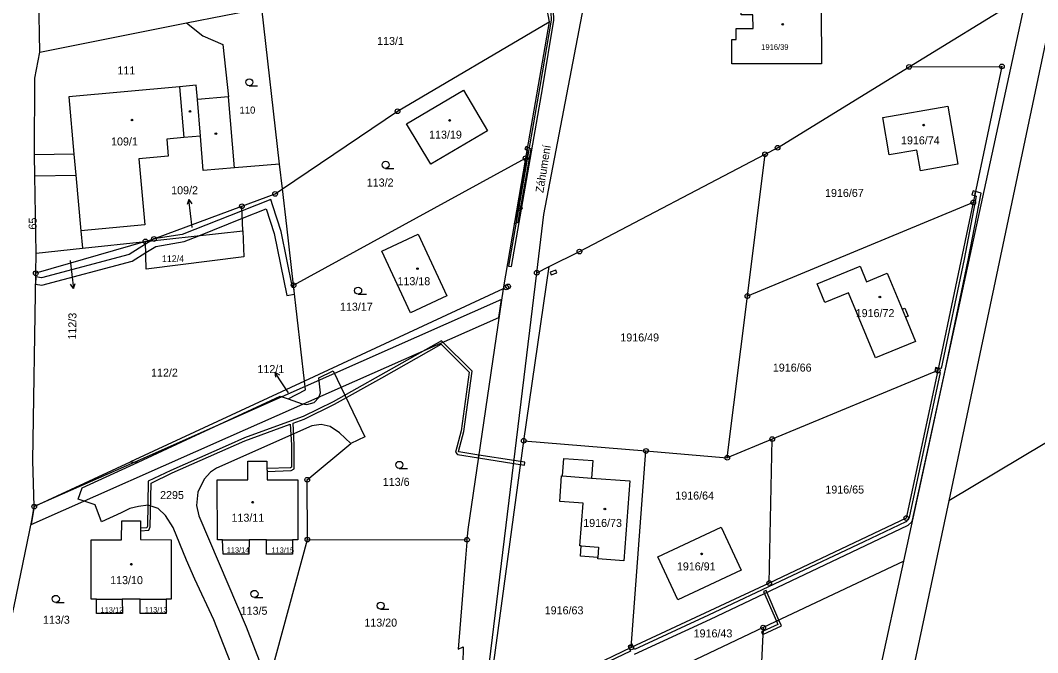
# Model space of a CAD drawing. Extents: x -504988 to -494607, y -1123820 to -1114018.
# Drawn here: x -497515.3 to -497299.3, y -1119789.7 to -1119655.4 of the extents above; entities that cross this region are included whole.
import ezdxf

# ---------------------------------------------------------------- set-up
doc = ezdxf.new("R2010")
doc.units = 0
for name, color, linetype in [('Hranice parcel', 7, 'Continuous'), ('Parcelní čísla', 7, 'Continuous'), ('Pop  PČ popisy', 7, 'Continuous'), ('Vnitřní kresba', 7, 'Continuous'), ('Věcná břemena k části', 7, 'Continuous'), ('Značky bodu BP', 7, 'Continuous'), ('Značky budov', 7, 'Continuous'), ('Značky kultur', 7, 'Continuous')]:
    doc.layers.add(name, color=color, linetype=linetype)

msp = doc.modelspace()

# ---------------------------------------------------------------- linework, layer by layer
at = {"layer": 'Hranice parcel'}
for p, q in [((-497407.59, -1119632.61), (-497403.06, -1119655.71)), ((-497511.18, -1119662.18), (-497511.51, -1119643.57)), ((-497327.77, -1119770.24), (-497301.66, -1119649.94)), ((-497326.62, -1119665.28), (-497301.66, -1119649.94)), ((-497480.03, -1119655.96), (-497464.09, -1119652.83)), ((-497460.28, -1119685.94), (-497464.09, -1119652.83)), ((-497511.18, -1119662.18), (-497480.03, -1119655.96)), ((-497403.06, -1119655.71), (-497408.06, -1119684.69)), ((-497326.62, -1119665.28), (-497306.93, -1119665.18)), ((-497306.93, -1119665.18), (-497313.01, -1119694.07)), ((-497457.32, -1119711.66), (-497408.06, -1119684.69)), ((-497408.06, -1119684.69), (-497412.84, -1119712.42)), ((-497360.96, -1119713.95), (-497357.22, -1119683.85)), ((-497459.67, -1119691.2), (-497460.28, -1119685.94)), ((-497313.01, -1119694.07), (-497360.96, -1119713.95)), ((-497313.01, -1119694.07), (-497320.56, -1119729.78)), ((-497468.09, -1119700.14), (-497468.28, -1119694.88)), ((-497488.77, -1119702.37), (-497468.09, -1119700.14)), ((-497488.77, -1119702.37), (-497512.06, -1119709.13)), ((-497502.14, -1119703.81), (-497488.77, -1119702.37)), ((-497512.06, -1119709.13), (-497511.99, -1119704.87)), ((-497511.99, -1119704.87), (-497502.14, -1119703.81)), ((-497409, -1119736.4), (-497405.68, -1119709.01)), ((-497408.46, -1119744.7), (-497403.07, -1119707.71)), ((-497405.68, -1119709.01), (-497403.07, -1119707.71)), ((-497454.98, -1119732), (-497457.32, -1119711.66)), ((-497412.84, -1119712.42), (-497454.98, -1119732)), ((-497365.23, -1119748.3), (-497360.96, -1119713.95)), ((-497320.56, -1119729.78), (-497355.7, -1119744.33)), ((-497454.98, -1119732), (-497491.96, -1119749.19)), ((-497481.05, -1119744.93), (-497460.19, -1119735.22)), ((-497460.19, -1119735.22), (-497458.47, -1119735.81)), ((-497458.47, -1119735.81), (-497455.5, -1119736.82)), ((-497418.3, -1119813.05), (-497409, -1119736.4)), ((-497490.32, -1119749.21), (-497481.05, -1119744.93)), ((-497408.46, -1119744.7), (-497382.5, -1119746.86)), ((-497355.7, -1119744.33), (-497365.23, -1119748.3)), ((-497356.32, -1119774.9), (-497355.7, -1119744.33)), ((-497385.64, -1119788.59), (-497382.5, -1119746.86)), ((-497382.5, -1119746.86), (-497365.23, -1119748.3)), ((-497512.39, -1119758.68), (-497491.96, -1119749.19)), ((-497502.18, -1119754.7), (-497490.32, -1119749.21)), ((-497491.96, -1119749.19), (-497490.32, -1119749.21)), ((-497472.38, -1119765.73), (-497466.78, -1119765.72)), ((-497463.05, -1119765.72), (-497466.78, -1119765.72)), ((-497463.05, -1119765.72), (-497457.52, -1119765.72)), ((-497463.02, -1119797.51), (-497454.39, -1119765.69)), ((-497454.39, -1119765.69), (-497420.5, -1119765.72)), ((-497327.77, -1119770.24), (-497357.6, -1119784.35)), ((-497340.35, -1119828.18), (-497327.77, -1119770.24)), ((-497356.32, -1119774.9), (-497385.64, -1119788.59)), ((-497499.15, -1119778.3), (-497493.68, -1119778.31)), ((-497489.92, -1119778.31), (-497493.68, -1119778.31)), ((-497489.92, -1119778.31), (-497484.34, -1119778.32)), ((-497357.6, -1119784.35), (-497379.24, -1119794.58)), ((-497357.6, -1119784.35), (-497360.12, -1119837.86))]:
    msp.add_line(p, q, dxfattribs=at)
for points in [[(-496164.18, -1119488.14), (-496312.79, -1119486.99), (-496461.39, -1119485.83), (-496579.64, -1119487.64), (-496697.89, -1119489.45), (-496849, -1119528.49), (-497000.1, -1119567.53), (-497159.17, -1119662.47), (-497318.23, -1119757.42)], [(-497359.78, -1119654.24), (-497362.29, -1119654.26), (-497362.28, -1119646.75), (-497348.25, -1119646.69), (-497348.23, -1119653.04), (-497345.27, -1119653.09), (-497345.26, -1119664.61), (-497364.27, -1119664.64), (-497364.26, -1119659.46), (-497363.35, -1119659.45), (-497363.37, -1119657.14), (-497359.76, -1119657.14), (-497359.78, -1119654.24)], [(-497295.06, -1119646.14), (-497295.74, -1119650.96), (-497318.23, -1119757.42)], [(-497405.68, -1119709.01), (-497404.18, -1119696.66), (-497395.06, -1119648.92)], [(-497480.03, -1119655.96), (-497476.56, -1119658.71), (-497472.36, -1119660.56), (-497471.12, -1119671.68)], [(-497459.67, -1119691.2), (-497435.24, -1119674.7), (-497403.06, -1119655.71)], [(-497511.99, -1119704.87), (-497512.23, -1119688.43), (-497512.34, -1119684), (-497512.24, -1119667.7), (-497511.18, -1119662.18)], [(-497357.22, -1119683.85), (-497354.55, -1119682.45), (-497326.62, -1119665.28)], [(-497471.12, -1119671.68), (-497477.75, -1119672.23), (-497478.01, -1119669.18), (-497481.57, -1119669.5), (-497505.05, -1119671.63), (-497503.95, -1119683.82), (-497503.54, -1119688.26), (-497502.47, -1119700.09), (-497502.14, -1119703.81)], [(-497433.34, -1119677.36), (-497421.27, -1119670.24), (-497416.16, -1119678.85), (-497428.21, -1119685.98), (-497433.34, -1119677.36)], [(-497460.28, -1119685.94), (-497469.86, -1119686.74), (-497471.12, -1119671.68)], [(-497324.18, -1119687.36), (-497325, -1119682.99), (-497330.89, -1119683.98), (-497332.21, -1119676.05), (-497318.41, -1119673.63), (-497316.27, -1119685.98), (-497324.18, -1119687.36)], [(-497403.07, -1119707.71), (-497396.63, -1119704.51), (-497357.22, -1119683.85)], [(-497468.28, -1119694.88), (-497461.23, -1119692.25), (-497459.67, -1119691.2)], [(-497457.32, -1119711.66), (-497458.76, -1119699.13), (-497459.67, -1119691.2)], [(-497488.77, -1119702.37), (-497486.96, -1119701.84), (-497468.28, -1119694.88)], [(-497468.09, -1119700.14), (-497467.89, -1119705.6), (-497488.61, -1119708.26), (-497488.77, -1119702.37)], [(-497438.56, -1119704.39), (-497430.87, -1119700.82), (-497424.76, -1119713.94), (-497432.46, -1119717.52), (-497438.56, -1119704.39)], [(-497512.39, -1119758.68), (-497512.67, -1119748.87), (-497512.06, -1119709.13)], [(-497339.49, -1119713.27), (-497344.54, -1119715.32), (-497346.17, -1119711.36), (-497337.03, -1119707.58), (-497335.67, -1119710.93), (-497331.29, -1119709.11), (-497328.11, -1119716.76), (-497327.55, -1119716.55), (-497326.85, -1119718.24), (-497327.4, -1119718.47), (-497325.28, -1119723.59), (-497333.77, -1119727.11), (-497339.49, -1119713.27)], [(-497412.84, -1119712.42), (-497420.32, -1119763.55), (-497420.5, -1119765.72)], [(-497455.5, -1119736.82), (-497454.51, -1119736.96), (-497452.95, -1119736.54), (-497451.93, -1119735.53), (-497451.62, -1119734.51), (-497451.99, -1119731.35), (-497448.94, -1119729.87), (-497442.2, -1119743.84), (-497445.14, -1119745.27)], [(-497320.56, -1119729.78), (-497327.23, -1119761.11), (-497356.32, -1119774.9)], [(-497458.47, -1119735.81), (-497454.76, -1119733.9), (-497454.98, -1119732)], [(-497445.14, -1119745.27), (-497447.56, -1119743), (-497449.56, -1119741.68), (-497451.47, -1119741.24), (-497453.43, -1119741.49), (-497473.67, -1119750.53), (-497474.95, -1119751.36), (-497476.27, -1119752.82), (-497477.67, -1119755.63), (-497477.95, -1119758.44), (-497477.45, -1119760.62), (-497475.19, -1119765.95), (-497467.37, -1119784.18), (-497464.3, -1119792.28), (-497463.02, -1119797.51)], [(-497454.39, -1119765.69), (-497454.42, -1119752.97), (-497445.14, -1119745.27)], [(-497385.64, -1119788.59), (-497399.15, -1119795.13), (-497401.06, -1119795.52), (-497411.99, -1119794.43), (-497413.82, -1119793.5), (-497414.82, -1119791.78), (-497408.46, -1119744.7)], [(-497472.38, -1119765.73), (-497473.5, -1119765.73), (-497473.53, -1119753.02), (-497471.1, -1119753.01), (-497467.01, -1119753), (-497467, -1119748.99), (-497463.01, -1119749.01), (-497462.92, -1119752.98), (-497456.42, -1119752.98), (-497456.39, -1119765.72), (-497457.52, -1119765.72)], [(-497396.52, -1119766.97), (-497395.83, -1119757.96), (-497400.82, -1119757.59), (-497400.41, -1119752.12), (-497400.21, -1119752.14), (-497399.93, -1119748.44), (-497393.78, -1119748.9), (-497394.06, -1119752.6), (-497385.9, -1119753.22), (-497387.19, -1119770.2), (-497392.74, -1119769.77), (-497392.72, -1119769.49), (-497396.41, -1119769.21), (-497396.23, -1119766.99), (-497396.52, -1119766.97)], [(-497468.93, -1119817.15), (-497469.03, -1119809.5), (-497469.23, -1119795.55), (-497474.27, -1119782.74), (-497478.31, -1119774.06), (-497480.05, -1119770.08), (-497482.92, -1119763.12), (-497484.5, -1119760.57), (-497486.1, -1119759.09), (-497488.21, -1119758.38), (-497490.23, -1119758.67), (-497492.1, -1119759.08), (-497493.9, -1119760.03), (-497498.09, -1119761.94), (-497499.43, -1119758.28), (-497503.05, -1119757.07), (-497502.18, -1119754.7)], [(-497521.65, -1119795.34), (-497517.82, -1119785.36), (-497516.64, -1119779.85), (-497512.87, -1119761.64), (-497512.39, -1119758.68)], [(-497318.23, -1119757.42), (-497329.15, -1119809.16), (-497330.48, -1119822.29)], [(-497499.15, -1119778.3), (-497500.29, -1119778.3), (-497500.29, -1119765.7), (-497493.82, -1119765.7), (-497493.8, -1119761.69), (-497489.83, -1119761.7), (-497489.82, -1119765.69), (-497483.29, -1119765.7), (-497483.31, -1119778.32), (-497484.34, -1119778.32)], [(-497379.98, -1119769.32), (-497366.56, -1119763.06), (-497362.32, -1119772.19), (-497375.74, -1119778.44), (-497379.98, -1119769.32)], [(-497466.78, -1119765.72), (-497466.81, -1119768.74), (-497472.28, -1119768.76), (-497472.38, -1119765.73)], [(-497457.52, -1119765.72), (-497457.52, -1119768.77), (-497463.04, -1119768.78), (-497463.05, -1119765.72)], [(-497420.5, -1119765.72), (-497420.54, -1119766.23), (-497420.81, -1119769.65), (-497422.37, -1119788.98)], [(-497493.68, -1119778.31), (-497493.65, -1119781.38), (-497499.15, -1119781.4), (-497499.15, -1119778.3)], [(-497484.34, -1119778.32), (-497484.37, -1119781.34), (-497489.92, -1119781.36), (-497489.92, -1119778.31)], [(-497422.37, -1119788.98), (-497421.31, -1119788.47), (-497421.37, -1119792.15)]]:
    msp.add_lwpolyline(points, dxfattribs=at)
at = {"layer": 'Pop  PČ popisy'}
for p, q in [((-497479.57, -1119693.47), (-497479.94, -1119694.53)), ((-497479.2, -1119696.45), (-497479.57, -1119693.47)), ((-497479.57, -1119693.47), (-497478.95, -1119694.4)), ((-497478.85, -1119699.43), (-497479.2, -1119696.45)), ((-497504.78, -1119706.38), (-497504.4, -1119709.35)), ((-497504.4, -1119709.35), (-497504.03, -1119712.33)), ((-497504.03, -1119712.33), (-497504.65, -1119711.4)), ((-497504.03, -1119712.33), (-497503.66, -1119711.27)), ((-497459.65, -1119732.61), (-497461.28, -1119730.09)), ((-497461.28, -1119730.09), (-497460.32, -1119730.66)), ((-497461.28, -1119730.09), (-497461.16, -1119731.21)), ((-497458.4, -1119734.53), (-497459.65, -1119732.61))]:
    msp.add_line(p, q, dxfattribs=at)
at = {"layer": 'Vnitřní kresba'}
for p, q in [((-497481.57, -1119669.5), (-497480.59, -1119680.32)), ((-497477.1, -1119680), (-497477.75, -1119672.23)), ((-497480.59, -1119680.32), (-497484.25, -1119680.65)), ((-497484.25, -1119680.65), (-497483.92, -1119684.28)), ((-497477.1, -1119680), (-497480.59, -1119680.32)), ((-497476.49, -1119687.3), (-497477.1, -1119680)), ((-497503.95, -1119683.82), (-497512.34, -1119684)), ((-497483.92, -1119684.28), (-497490.16, -1119684.84)), ((-497490.16, -1119684.84), (-497488.89, -1119698.86)), ((-497469.86, -1119686.74), (-497476.49, -1119687.3)), ((-497512.23, -1119688.43), (-497503.54, -1119688.26)), ((-497488.89, -1119698.86), (-497502.47, -1119700.09)), ((-497328.11, -1119716.76), (-497327.4, -1119718.47)), ((-497400.21, -1119752.14), (-497394.06, -1119752.6)), ((-497396.23, -1119766.99), (-497392.55, -1119767.28)), ((-497392.55, -1119767.28), (-497392.72, -1119769.49))]:
    msp.add_line(p, q, dxfattribs=at)
at = {"layer": 'Věcná břemena k části'}
for points in [[(-497402.66, -1119655.35), (-497405, -1119669.46), (-497411.67, -1119707.6), (-497411.08, -1119707.71), (-497404.4, -1119669.56), (-497402.06, -1119655.39), (-497402.15, -1119653.28), (-497403.66, -1119652.63), (-497403.52, -1119653.35), (-497402.73, -1119653.68)], [(-497407.76, -1119682.98), (-497407.53, -1119683.11), (-497410.13, -1119697.85), (-497410.34, -1119697.92), (-497410.46, -1119698.59), (-497409.6, -1119698.3), (-497406.87, -1119682.79), (-497407.66, -1119682.35)], [(-497407.76, -1119682.98), (-497407.66, -1119682.35), (-497407.93, -1119682.2), (-497408.22, -1119682.72)], [(-497312.52, -1119691.73), (-497313.05, -1119691.58), (-497313.3, -1119692.45), (-497312.71, -1119692.62)], [(-497458.77, -1119713.81), (-497457.1, -1119713.58), (-497457.27, -1119712.09), (-497457.57, -1119712.13), (-497459.96, -1119700.26), (-497461.74, -1119694.8), (-497462.18, -1119693.45), (-497468.24, -1119695.86), (-497480.95, -1119700.92), (-497486.96, -1119701.84), (-497487.61, -1119702.24), (-497488.75, -1119702.96), (-497492.22, -1119705.12), (-497510.84, -1119710.09), (-497512.07, -1119709.88), (-497512.09, -1119711.4), (-497510.76, -1119711.63), (-497491.62, -1119706.52), (-497488.71, -1119704.72), (-497486.58, -1119703.4), (-497480.53, -1119702.38), (-497477.45, -1119701.15), (-497468.19, -1119697.45), (-497463.12, -1119695.43), (-497461.42, -1119700.64)], [(-497402.65, -1119709.43), (-497401.46, -1119709.01), (-497401.66, -1119708.45), (-497402.85, -1119708.87)], [(-497413.17, -1119714.67), (-497454.85, -1119733.16), (-497491.03, -1119749.2), (-497512.39, -1119758.68), (-497512.87, -1119761.64), (-497513.04, -1119762.45), (-497471.21, -1119743.93), (-497413.73, -1119718.48)], [(-497487.77, -1119762.95), (-497487.57, -1119753.68), (-497483.11, -1119751.51), (-497471.18, -1119746.27), (-497467.69, -1119744.73), (-497458.04, -1119741.19), (-497457.78, -1119745.55), (-497457.78, -1119750.29), (-497458, -1119750.42), (-497462.97, -1119750.6), (-497462.96, -1119751.2), (-497457.82, -1119751.02), (-497457.18, -1119750.62), (-497457.18, -1119745.53), (-497457.44, -1119740.97), (-497455.06, -1119740.11), (-497448.6, -1119736.94), (-497438.55, -1119731.29), (-497426.01, -1119724.21), (-497420.02, -1119730.15), (-497421.77, -1119742.57), (-497422.95, -1119747.08), (-497422.54, -1119747.62), (-497418.09, -1119748.31), (-497418, -1119747.72), (-497422.2, -1119747.06), (-497422.29, -1119746.94), (-497421.19, -1119742.69), (-497419.38, -1119729.93), (-497425.91, -1119723.47), (-497438.85, -1119730.77), (-497448.88, -1119736.4), (-497455.3, -1119739.55), (-497457.85, -1119740.48), (-497467.74, -1119744.1), (-497471.19, -1119745.62), (-497483.37, -1119750.97), (-497488.17, -1119753.3), (-497488.37, -1119762.83), (-497488.5, -1119763.15), (-497489.83, -1119763.25), (-497489.82, -1119763.85), (-497488.08, -1119763.71)], [(-497320.56, -1119729.78), (-497320.45, -1119729.24), (-497321.03, -1119729.15), (-497321.17, -1119730.03)], [(-497418, -1119747.72), (-497418.09, -1119748.31), (-497410.59, -1119749.49), (-497408.31, -1119749.84), (-497408.22, -1119749.25), (-497410.52, -1119748.89)], [(-497354.81, -1119783.03), (-497354.27, -1119782.77), (-497356.96, -1119776.46), (-497357.52, -1119776.7)], [(-497354.81, -1119783.03), (-497354.53, -1119783.68), (-497357.64, -1119785.16), (-497357.67, -1119785.84), (-497353.75, -1119783.97), (-497354.27, -1119782.77)], [(-497357.67, -1119785.84), (-497357.64, -1119785.16), (-497357.95, -1119785.31)], [(-497385.59, -1119787.94), (-497386.28, -1119788.26), (-497386.04, -1119788.78), (-497385.64, -1119788.59)], [(-497385.59, -1119787.94), (-497385.64, -1119788.59), (-497385.22, -1119788.4), (-497385.46, -1119787.88)]]:
    msp.add_lwpolyline(points, close=True, dxfattribs=at)
msp.add_lwpolyline([(-497384.97, -1119790.02), (-497368.81, -1119782.58), (-497335.88, -1119766.94), (-497326.84, -1119762.64), (-497326.15, -1119761.98), (-497325.88, -1119761.52), (-497318.99, -1119729.77), (-497314.08, -1119706.31), (-497311.33, -1119692.08), (-497312.52, -1119691.73), (-497312.71, -1119692.62), (-497312.37, -1119692.72), (-497314.96, -1119706.13), (-497319.84, -1119729.34), (-497320.45, -1119729.24), (-497320.56, -1119729.78), (-497320.63, -1119730.12), (-497320.03, -1119730.22), (-497326.6, -1119760.97), (-497326.87, -1119761.42), (-497327.36, -1119761.9), (-497336.26, -1119766.12), (-497369.19, -1119781.76), (-497384.94, -1119789.01), (-497385.22, -1119788.4), (-497385.64, -1119788.59), (-497386.04, -1119788.78), (-497385.75, -1119789.39), (-497399.55, -1119795.96)], dxfattribs=at)
at = {"layer": 'Značky bodu BP'}
for centre, radius in [((-497326.62, -1119665.28), 0.5), ((-497326.62, -1119665.28), 0.0303), ((-497306.93, -1119665.18), 0.5), ((-497306.93, -1119665.18), 0.0303), ((-497435.24, -1119674.7), 0.5), ((-497435.24, -1119674.7), 0.0303), ((-497357.22, -1119683.85), 0.5), ((-497354.55, -1119682.45), 0.5), ((-497354.55, -1119682.45), 0.0303), ((-497408.06, -1119684.69), 0.5), ((-497408.06, -1119684.69), 0.0303), ((-497357.22, -1119683.85), 0.0303), ((-497461.23, -1119692.25), 0.5), ((-497461.23, -1119692.25), 0.0303), ((-497313.01, -1119694.07), 0.5), ((-497313.01, -1119694.07), 0.0303), ((-497468.28, -1119694.88), 0.5), ((-497468.28, -1119694.88), 0.0303), ((-497409.32, -1119695.32), 0.5), ((-497409.32, -1119695.32), 0.0303), ((-497488.77, -1119702.37), 0.5), ((-497488.77, -1119702.37), 0.0303), ((-497486.96, -1119701.84), 0.5), ((-497486.96, -1119701.84), 0.0303), ((-497396.63, -1119704.51), 0.5), ((-497396.63, -1119704.51), 0.0303), ((-497512.06, -1119709.13), 0.5), ((-497512.06, -1119709.13), 0.0303), ((-497405.68, -1119709.01), 0.5), ((-497405.68, -1119709.01), 0.0303), ((-497457.32, -1119711.66), 0.5), ((-497411.77, -1119711.92), 0.5), ((-497457.32, -1119711.66), 0.0303), ((-497412.18, -1119712.11), 0.5), ((-497412.18, -1119712.11), 0.0303), ((-497411.77, -1119711.92), 0.0303), ((-497360.96, -1119713.95), 0.5), ((-497360.96, -1119713.95), 0.0303), ((-497320.56, -1119729.78), 0.5), ((-497320.56, -1119729.78), 0.0303), ((-497355.7, -1119744.33), 0.5), ((-497408.46, -1119744.7), 0.5), ((-497408.46, -1119744.7), 0.0303), ((-497355.7, -1119744.33), 0.0303), ((-497382.5, -1119746.86), 0.5), ((-497382.5, -1119746.86), 0.0303), ((-497365.23, -1119748.3), 0.5), ((-497365.23, -1119748.3), 0.0303), ((-497454.42, -1119752.97), 0.5), ((-497454.42, -1119752.97), 0.0303), ((-497512.39, -1119758.68), 0.5), ((-497512.39, -1119758.68), 0.0303), ((-497327.23, -1119761.11), 0.5), ((-497327.23, -1119761.11), 0.0303), ((-497454.39, -1119765.69), 0.5), ((-497420.5, -1119765.72), 0.5), ((-497454.39, -1119765.69), 0.0303), ((-497420.5, -1119765.72), 0.0303), ((-497356.32, -1119774.9), 0.5), ((-497356.32, -1119774.9), 0.0303), ((-497357.6, -1119784.35), 0.5), ((-497357.6, -1119784.35), 0.0303), ((-497385.64, -1119788.59), 0.5), ((-497385.64, -1119788.59), 0.0303)]:
    msp.add_circle(centre, radius, dxfattribs=at)
at = {"layer": 'Značky budov'}
for centre in [(-497353.46, -1119656.25), (-497479.32, -1119674.75), (-497491.63, -1119676.57), (-497424.18, -1119676.67), (-497323.53, -1119677.66), (-497473.81, -1119679.48), (-497431.01, -1119708.15), (-497332.84, -1119714.17), (-497466, -1119757.74), (-497391.23, -1119759.19), (-497370.68, -1119768.71), (-497491.76, -1119770.9)]:
    msp.add_circle(centre, 0.175, dxfattribs=at)
at = {"layer": 'Značky kultur'}
for p, q in [((-497466.72, -1119669.31), (-497464.97, -1119669.31)), ((-497437.78, -1119686.84), (-497436.03, -1119686.84)), ((-497443.62, -1119713.56), (-497441.87, -1119713.56)), ((-497434.87, -1119750.57), (-497433.12, -1119750.57)), ((-497465.62, -1119777.96), (-497463.87, -1119777.96)), ((-497507.8, -1119779.02), (-497506.05, -1119779.02)), ((-497438.84, -1119780.46), (-497437.09, -1119780.46))]:
    msp.add_line(p, q, dxfattribs=at)
for centre in [(-497466.72, -1119668.56), (-497437.78, -1119686.09), (-497443.62, -1119712.81), (-497434.87, -1119749.82), (-497507.8, -1119778.27), (-497465.62, -1119777.21), (-497438.84, -1119779.71)]:
    msp.add_circle(centre, 0.75, dxfattribs=at)

# ---------------------------------------------------------------- texts
at = {"layer": 'Parcelní čísla'}
for s, height, p in [('113/1', 1.7, (-497439.58, -1119660.63)), ('1916/39', 1.2, (-497358.03, -1119661.68)), ('111', 1.7, (-497494.72, -1119666.89)), ('110', 1.5, (-497468.79, -1119675.21)), ('113/19', 1.7, (-497428.55, -1119680.53)), ('109/1', 1.7, (-497496.07, -1119681.98)), ('1916/74', 1.7, (-497328.35, -1119681.74)), ('113/2', 1.7, (-497441.78, -1119690.7)), ('109/2', 1.7, (-497483.31, -1119692.34)), ('1916/67', 1.7, (-497344.48, -1119692.91)), ('112/4', 1.4, (-497485.26, -1119706.72)), ('113/18', 1.7, (-497435.26, -1119711.65)), ('113/17', 1.7, (-497447.47, -1119717.07)), ('1916/72', 1.7, (-497337.97, -1119718.43)), ('1916/49', 1.7, (-497387.94, -1119723.6)), ('112/1', 1.7, (-497464.99, -1119730.31)), ('1916/66', 1.7, (-497355.56, -1119730)), ('112/2', 1.7, (-497487.58, -1119731.07)), ('113/6', 1.7, (-497438.38, -1119754.27)), ('1916/65', 1.7, (-497344.41, -1119755.9)), ('2295', 1.7, (-497485.66, -1119757.07)), ('1916/64', 1.7, (-497376.27, -1119757.18)), ('113/11', 1.7, (-497470.5, -1119761.88)), ('1916/73', 1.7, (-497395.82, -1119762.99)), ('113/14', 1.139, (-497471.52, -1119768.45)), ('113/15', 1.139, (-497462.02, -1119768.49)), ('1916/91', 1.7, (-497375.93, -1119772.22)), ('113/10', 1.7, (-497496.26, -1119775.14)), ('113/12', 1.139, (-497498.3, -1119781.19)), ('113/13', 1.139, (-497488.89, -1119781.16)), ('113/5', 1.7, (-497468.56, -1119781.64)), ('1916/63', 1.7, (-497404, -1119781.55)), ('113/3', 1.7, (-497510.53, -1119783.55)), ('113/20', 1.7, (-497442.29, -1119784.16)), ('1916/43', 1.7, (-497372.38, -1119786.45))]:
    msp.add_text(s, height=height, dxfattribs=at).set_placement(p)
for s, p in [('65', (-497511.89, -1119699.84)), ('112/3', (-497503.51, -1119723.21))]:
    msp.add_text(s, height=1.7, rotation=89, dxfattribs=at).set_placement(p)
at = {"layer": 'Pop  PČ popisy'}
msp.add_text('Záhumení', height=1.7, rotation=81, dxfattribs=at).set_placement((-497404.3, -1119692.13))

doc.saveas('drawing.dxf')
